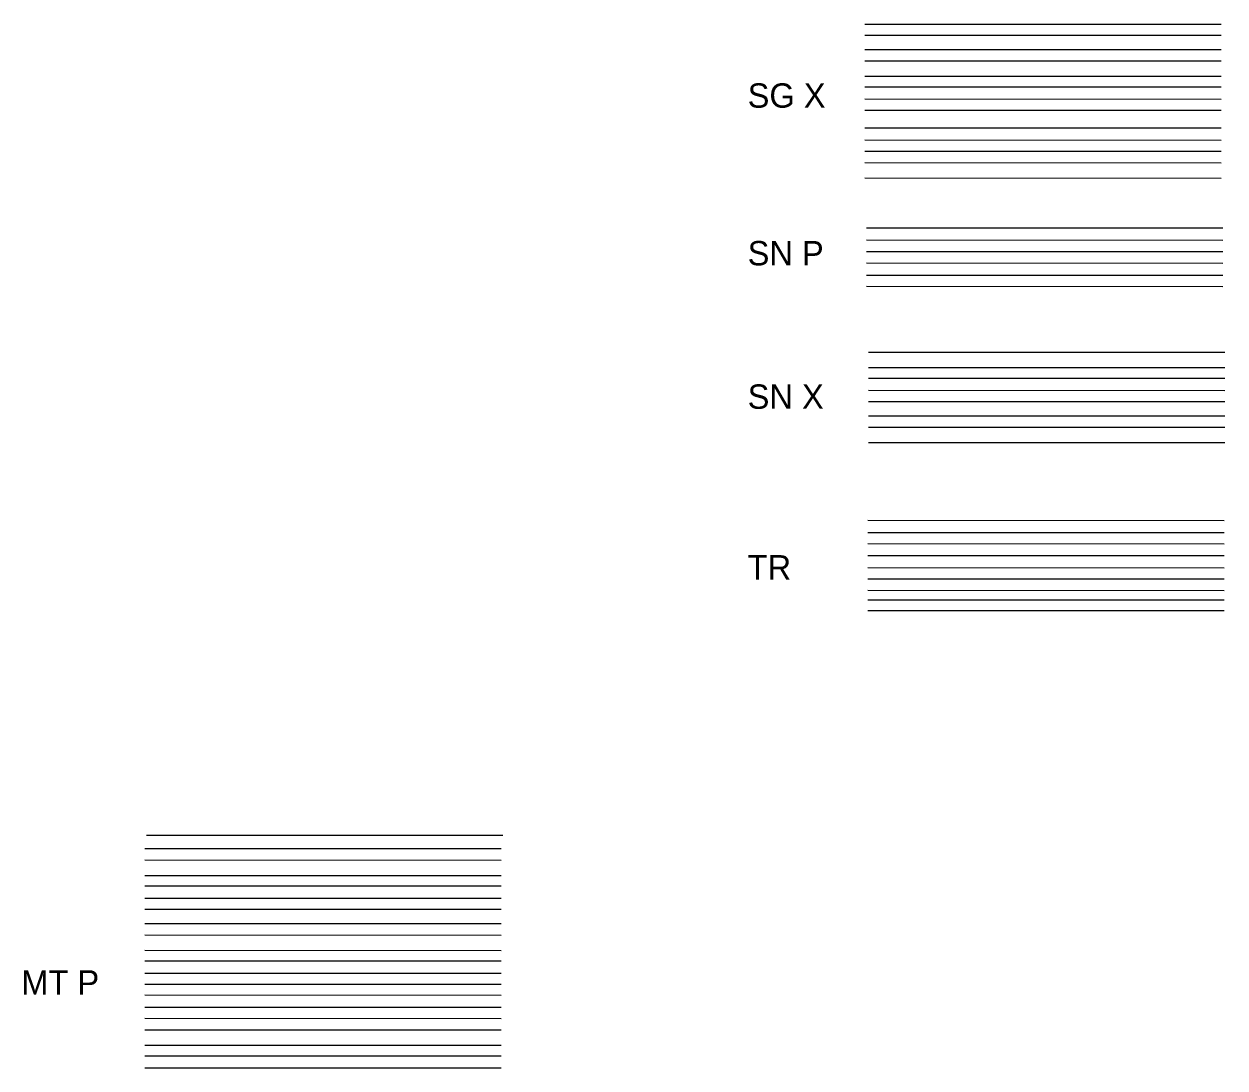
# Model space of a CAD drawing. Extents: x 19437 to 1370217, y 6871 to 405972.
# Drawn here: x 19437 to 22394, y 9484 to 12055 of the extents above; entities that cross this region are included whole.
import ezdxf

# ---------------------------------------------------------------- set-up
doc = ezdxf.new("R2010")
doc.units = 0
for name, color, linetype in [('Default', 7, 'Continuous'), ('MT_P_Cells', 7, 'Continuous'), ('MT_P_Channelizing_Line', 7, 'Continuous'), ('MT_P_CL_Dashed', 7, 'Continuous'), ('MT_P_CL_Dashed_II', 7, 'Continuous'), ('MT_P_CL_Double_Solid', 7, 'Continuous'), ('MT_P_CL_Pass_Proh_LT', 7, 'Continuous'), ('MT_P_CL_Pass_Proh_RT', 7, 'Continuous'), ('MT_P_Crosswalk_Line', 7, 'Continuous'), ('MT_P_Dotted_Line', 7, 'Continuous'), ('MT_P_Drums', 7, 'Continuous'), ('MT_P_Edge_Line', 7, 'Continuous'), ('MT_P_Gore_Marking', 7, 'Continuous'), ('MT_P_GR_Bar', 7, 'Continuous'), ('MT_P_GR_Lt', 7, 'Continuous'), ('MT_P_GR_Rt', 7, 'Continuous'), ('MT_P_Island', 7, 'Continuous'), ('MT_P_Lane_Line', 7, 'Continuous'), ('MT_P_Lane_Line_II', 7, 'Continuous'), ('MT_P_PCB', 7, 'Continuous'), ('MT_P_Transverse_Line', 7, 'Continuous'), ('SG_X_Conduit', 7, 'Continuous'), ('SG_X_Controllers', 7, 'Continuous'), ('SG_X_Detection', 7, 'Continuous'), ('SG_X_Foundation', 7, 'Continuous'), ('SG_X_Heads', 7, 'Continuous'), ('SG_X_Interconnect_Cable', 7, 'Continuous'), ('SG_X_Manhole', 7, 'Continuous'), ('SG_X_Mast_Arm', 7, 'Continuous'), ('SG_X_Messenger_Wire', 7, 'Continuous'), ('SG_X_Poles', 7, 'Continuous'), ('SG_X_PullBox', 7, 'Continuous'), ('SG_X_Text', 7, 'Continuous'), ('SG_X_Wiring', 7, 'Continuous'), ('SN_P_Cantilever_Overhead', 7, 'Continuous'), ('SN_P_Foundation', 7, 'Continuous'), ('SN_P_Signs', 7, 'Continuous'), ('SN_P_Structure_Mount', 7, 'Continuous'), ('SN_P_Text', 7, 'Continuous'), ('SN_P_Truss_Overhead', 7, 'Continuous'), ('SN_X_Billboard', 7, 'Continuous'), ('SN_X_Cantilever_Overhead', 7, 'Continuous'), ('SN_X_Foundation', 7, 'Continuous'), ('SN_X_Private', 7, 'Continuous'), ('SN_X_Public', 7, 'Continuous'), ('SN_X_Structure_Mount', 7, 'Continuous'), ('SN_X_Text', 7, 'Continuous'), ('SN_X_Truss_Overhead', 7, 'Continuous'), ('TR_Text', 7, 'Continuous'), ('TR_Turning_Path1', 7, 'Continuous'), ('TR_Turning_Path2', 7, 'Continuous'), ('TR_Turning_Path3', 7, 'Continuous'), ('TR_Turning_Path4', 7, 'Continuous'), ('TR_Turning_Path5', 7, 'Continuous'), ('TR_Turning_Path6', 7, 'Continuous'), ('TR_Turning_Path7', 7, 'Continuous'), ('TR_Turning_Path8', 7, 'Continuous')]:
    doc.layers.add(name, color=color, linetype=linetype)

msp = doc.modelspace()

# ---------------------------------------------------------------- linework, layer by layer
at = {"layer": 'MT_P_Cells'}
msp.add_lwpolyline([(19734.8, 10024.7), (19734.8, 10024.7), (20612.1, 10024.5), (20612.1, 10024.5)], dxfattribs=at)
at = {"layer": 'MT_P_Channelizing_Line'}
msp.add_lwpolyline([(19734.8, 9996.4), (19734.8, 9996.4), (20612.1, 9996.2), (20612.1, 9996.2)], dxfattribs=at)
at = {"layer": 'MT_P_CL_Dashed'}
msp.add_lwpolyline([(19734.8, 9958.6), (19734.8, 9958.6), (20612.1, 9958.4), (20612.1, 9958.4)], dxfattribs=at)
at = {"layer": 'MT_P_CL_Dashed_II'}
msp.add_lwpolyline([(19734.8, 9932.6), (19734.8, 9932.6), (20612.1, 9932.4), (20612.1, 9932.4)], dxfattribs=at)
at = {"layer": 'MT_P_CL_Double_Solid'}
msp.add_lwpolyline([(19734.8, 9902.6), (19734.8, 9902.6), (20612.1, 9902.4), (20612.1, 9902.4)], dxfattribs=at)
at = {"layer": 'MT_P_CL_Pass_Proh_LT'}
msp.add_lwpolyline([(19734.8, 9875.2), (19734.8, 9875.2), (20612.1, 9875), (20612.1, 9875)], dxfattribs=at)
at = {"layer": 'MT_P_CL_Pass_Proh_RT'}
msp.add_lwpolyline([(19734.8, 9840.1), (19734.8, 9840.1), (20612.1, 9839.9), (20612.1, 9839.9)], dxfattribs=at)
at = {"layer": 'MT_P_Crosswalk_Line'}
msp.add_lwpolyline([(19734.8, 9811.8), (19734.8, 9811.8), (20612.1, 9811.6), (20612.1, 9811.6)], dxfattribs=at)
at = {"layer": 'MT_P_Dotted_Line'}
msp.add_lwpolyline([(19734.8, 9774), (19734.8, 9774), (20612.1, 9773.8), (20612.1, 9773.8)], dxfattribs=at)
at = {"layer": 'MT_P_Drums'}
msp.add_lwpolyline([(19734.8, 9748), (19734.8, 9748), (20612.1, 9747.8), (20612.1, 9747.8)], dxfattribs=at)
at = {"layer": 'MT_P_Edge_Line'}
msp.add_lwpolyline([(19734.8, 9718), (19734.8, 9718), (20612.1, 9717.8), (20612.1, 9717.8)], dxfattribs=at)
at = {"layer": 'MT_P_Gore_Marking'}
msp.add_lwpolyline([(19734.8, 9690.6), (19734.8, 9690.6), (20612.1, 9690.4), (20612.1, 9690.4)], dxfattribs=at)
at = {"layer": 'MT_P_GR_Bar'}
msp.add_lwpolyline([(19734.8, 9664), (19734.8, 9664), (20612.1, 9663.7), (20612.1, 9663.7)], dxfattribs=at)
at = {"layer": 'MT_P_GR_Lt'}
msp.add_lwpolyline([(19734.8, 9634), (19734.8, 9634), (20612.1, 9633.8), (20612.1, 9633.8)], dxfattribs=at)
at = {"layer": 'MT_P_GR_Rt'}
msp.add_lwpolyline([(19734.8, 9606.6), (19734.8, 9606.6), (20612.1, 9606.4), (20612.1, 9606.4)], dxfattribs=at)
at = {"layer": 'MT_P_Island'}
msp.add_lwpolyline([(19734.8, 9578.3), (19734.8, 9578.3), (20612.1, 9578.1), (20612.1, 9578.1)], dxfattribs=at)
at = {"layer": 'MT_P_Lane_Line'}
msp.add_lwpolyline([(19734.8, 9540.6), (19734.8, 9540.6), (20612.1, 9540.3), (20612.1, 9540.3)], dxfattribs=at)
at = {"layer": 'MT_P_Lane_Line_II'}
msp.add_lwpolyline([(19734.8, 9514.5), (19734.8, 9514.5), (20612.1, 9514.3), (20612.1, 9514.3)], dxfattribs=at)
at = {"layer": 'MT_P_PCB'}
msp.add_lwpolyline([(19734.8, 9484.5), (19734.8, 9484.5), (20612.1, 9484.3), (20612.1, 9484.3)], dxfattribs=at)
at = {"layer": 'MT_P_Transverse_Line'}
msp.add_lwpolyline([(19738.8, 10057.7), (19738.8, 10057.7), (20616.1, 10057.5), (20616.1, 10057.5)], dxfattribs=at)
at = {"layer": 'SG_X_Conduit'}
msp.add_lwpolyline([(21507.5, 12054.7), (21507.5, 12054.7), (22384.8, 12054.4), (22384.8, 12054.4)], dxfattribs=at)
at = {"layer": 'SG_X_Controllers'}
msp.add_lwpolyline([(21507.5, 12027.3), (21507.5, 12027.3), (22384.8, 12027.1), (22384.8, 12027.1)], dxfattribs=at)
at = {"layer": 'SG_X_Detection'}
msp.add_lwpolyline([(21507.5, 11992.2), (21507.5, 11992.2), (22384.8, 11992), (22384.8, 11992)], dxfattribs=at)
at = {"layer": 'SG_X_Foundation'}
msp.add_lwpolyline([(21507.5, 11963.9), (21507.5, 11963.9), (22384.8, 11963.7), (22384.8, 11963.7)], dxfattribs=at)
at = {"layer": 'SG_X_Heads'}
msp.add_lwpolyline([(21507.5, 11926.1), (21507.5, 11926.1), (22384.8, 11925.9), (22384.8, 11925.9)], dxfattribs=at)
at = {"layer": 'SG_X_Interconnect_Cable'}
msp.add_lwpolyline([(21507.5, 11900), (21507.5, 11900), (22384.8, 11899.8), (22384.8, 11899.8)], dxfattribs=at)
at = {"layer": 'SG_X_Manhole'}
msp.add_lwpolyline([(21507.5, 11870.1), (21507.5, 11870.1), (22384.8, 11869.9), (22384.8, 11869.9)], dxfattribs=at)
at = {"layer": 'SG_X_Mast_Arm'}
msp.add_lwpolyline([(21507.5, 11842.7), (21507.5, 11842.7), (22384.8, 11842.5), (22384.8, 11842.5)], dxfattribs=at)
at = {"layer": 'SG_X_Messenger_Wire'}
msp.add_lwpolyline([(21507.5, 11799.1), (21507.5, 11799.1), (22384.8, 11798.9), (22384.8, 11798.9)], dxfattribs=at)
at = {"layer": 'SG_X_Poles'}
msp.add_lwpolyline([(21507.5, 11769.1), (21507.5, 11769.1), (22384.8, 11768.9), (22384.8, 11768.9)], dxfattribs=at)
at = {"layer": 'SG_X_PullBox'}
msp.add_lwpolyline([(21507.5, 11741.7), (21507.5, 11741.7), (22384.8, 11741.5), (22384.8, 11741.5)], dxfattribs=at)
at = {"layer": 'SG_X_Text'}
msp.add_lwpolyline([(21507.5, 11713.5), (21507.5, 11713.5), (22384.8, 11713.2), (22384.8, 11713.2)], dxfattribs=at)
at = {"layer": 'SG_X_Wiring'}
msp.add_lwpolyline([(21507.5, 11675.7), (21507.5, 11675.7), (22384.8, 11675.5), (22384.8, 11675.5)], dxfattribs=at)
at = {"layer": 'SN_P_Cantilever_Overhead'}
msp.add_lwpolyline([(21511.7, 11552.9), (21511.7, 11552.9), (22389, 11552.7), (22389, 11552.7)], dxfattribs=at)
at = {"layer": 'SN_P_Foundation'}
msp.add_lwpolyline([(21511.7, 11522.9), (21511.7, 11522.9), (22389, 11522.7), (22389, 11522.7)], dxfattribs=at)
at = {"layer": 'SN_P_Signs'}
msp.add_lwpolyline([(21511.7, 11494.4), (21511.7, 11494.4), (22389, 11494.2), (22389, 11494.2)], dxfattribs=at)
at = {"layer": 'SN_P_Structure_Mount'}
msp.add_lwpolyline([(21511.7, 11466.4), (21511.7, 11466.4), (22389, 11466.2), (22389, 11466.2)], dxfattribs=at)
at = {"layer": 'SN_P_Text'}
msp.add_lwpolyline([(21511.7, 11436.4), (21511.7, 11436.4), (22389, 11436.2), (22389, 11436.2)], dxfattribs=at)
at = {"layer": 'SN_P_Truss_Overhead'}
msp.add_lwpolyline([(21511.7, 11409), (21511.7, 11409), (22389, 11408.8), (22389, 11408.8)], dxfattribs=at)
at = {"layer": 'SN_X_Billboard'}
msp.add_lwpolyline([(21516.7, 11246.7), (21516.7, 11246.7), (22393.9, 11246.4), (22393.9, 11246.4)], dxfattribs=at)
at = {"layer": 'SN_X_Cantilever_Overhead'}
msp.add_lwpolyline([(21516.7, 11208.9), (21516.7, 11208.9), (22393.9, 11208.7), (22393.9, 11208.7)], dxfattribs=at)
at = {"layer": 'SN_X_Foundation'}
msp.add_lwpolyline([(21516.7, 11182.8), (21516.7, 11182.8), (22393.9, 11182.6), (22393.9, 11182.6)], dxfattribs=at)
at = {"layer": 'SN_X_Private'}
msp.add_lwpolyline([(21516.7, 11152.8), (21516.7, 11152.8), (22393.9, 11152.6), (22393.9, 11152.6)], dxfattribs=at)
at = {"layer": 'SN_X_Public'}
msp.add_lwpolyline([(21516.7, 11125.5), (21516.7, 11125.5), (22393.9, 11125.2), (22393.9, 11125.2)], dxfattribs=at)
at = {"layer": 'SN_X_Structure_Mount'}
msp.add_lwpolyline([(21516.7, 11090.3), (21516.7, 11090.3), (22393.9, 11090.1), (22393.9, 11090.1)], dxfattribs=at)
at = {"layer": 'SN_X_Text'}
msp.add_lwpolyline([(21516.7, 11062.1), (21516.7, 11062.1), (22393.9, 11061.9), (22393.9, 11061.9)], dxfattribs=at)
at = {"layer": 'SN_X_Truss_Overhead'}
msp.add_lwpolyline([(21516.7, 11024.3), (21516.7, 11024.3), (22393.9, 11024.1), (22393.9, 11024.1)], dxfattribs=at)
at = {"layer": 'TR_Text'}
msp.add_lwpolyline([(21514.6, 10832.8), (21514.6, 10832.8), (22391.8, 10832.6), (22391.8, 10832.6)], dxfattribs=at)
at = {"layer": 'TR_Turning_Path1'}
msp.add_lwpolyline([(21514.6, 10802.8), (21514.6, 10802.8), (22391.8, 10802.6), (22391.8, 10802.6)], dxfattribs=at)
at = {"layer": 'TR_Turning_Path2'}
msp.add_lwpolyline([(21514.6, 10775.5), (21514.6, 10775.5), (22391.8, 10775.2), (22391.8, 10775.2)], dxfattribs=at)
at = {"layer": 'TR_Turning_Path3'}
msp.add_lwpolyline([(21514.6, 10746.2), (21514.6, 10746.2), (22391.8, 10745.9), (22391.8, 10745.9)], dxfattribs=at)
at = {"layer": 'TR_Turning_Path4'}
msp.add_lwpolyline([(21514.6, 10716.2), (21514.6, 10716.2), (22391.8, 10716), (22391.8, 10716)], dxfattribs=at)
at = {"layer": 'TR_Turning_Path5'}
msp.add_lwpolyline([(21514.6, 10688.8), (21514.6, 10688.8), (22391.8, 10688.6), (22391.8, 10688.6)], dxfattribs=at)
at = {"layer": 'TR_Turning_Path6'}
msp.add_lwpolyline([(21514.6, 10660.6), (21514.6, 10660.6), (22391.8, 10660.3), (22391.8, 10660.3)], dxfattribs=at)
at = {"layer": 'TR_Turning_Path7'}
msp.add_lwpolyline([(21514.6, 10637.1), (21514.6, 10637.1), (22391.8, 10636.9), (22391.8, 10636.9)], dxfattribs=at)
at = {"layer": 'TR_Turning_Path8'}
msp.add_lwpolyline([(21514.6, 10611), (21514.6, 10611), (22391.8, 10610.8), (22391.8, 10610.8)], dxfattribs=at)

# ---------------------------------------------------------------- texts
at = {"layer": 'Default'}
for s, p in [('SG X', (21218.8, 11848.6)), ('SN P', (21218.8, 11460.4)), ('SN X', (21218.8, 11107.3)), ('TR', (21218.8, 10687)), ('MT P', (19430.6, 9664.9))]:
    msp.add_text(s, height=60, dxfattribs=at).set_placement(p)

doc.saveas('drawing.dxf')
